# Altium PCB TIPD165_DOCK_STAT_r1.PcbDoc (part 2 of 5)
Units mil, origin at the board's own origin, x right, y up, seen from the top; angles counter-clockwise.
Board outline 6950 x 2800 mil, 2 copper layers (Primary Side, Secondary Side), stack 12.7 mil thick; 32 components, 163 nets, 1211 pads, 80 vias.
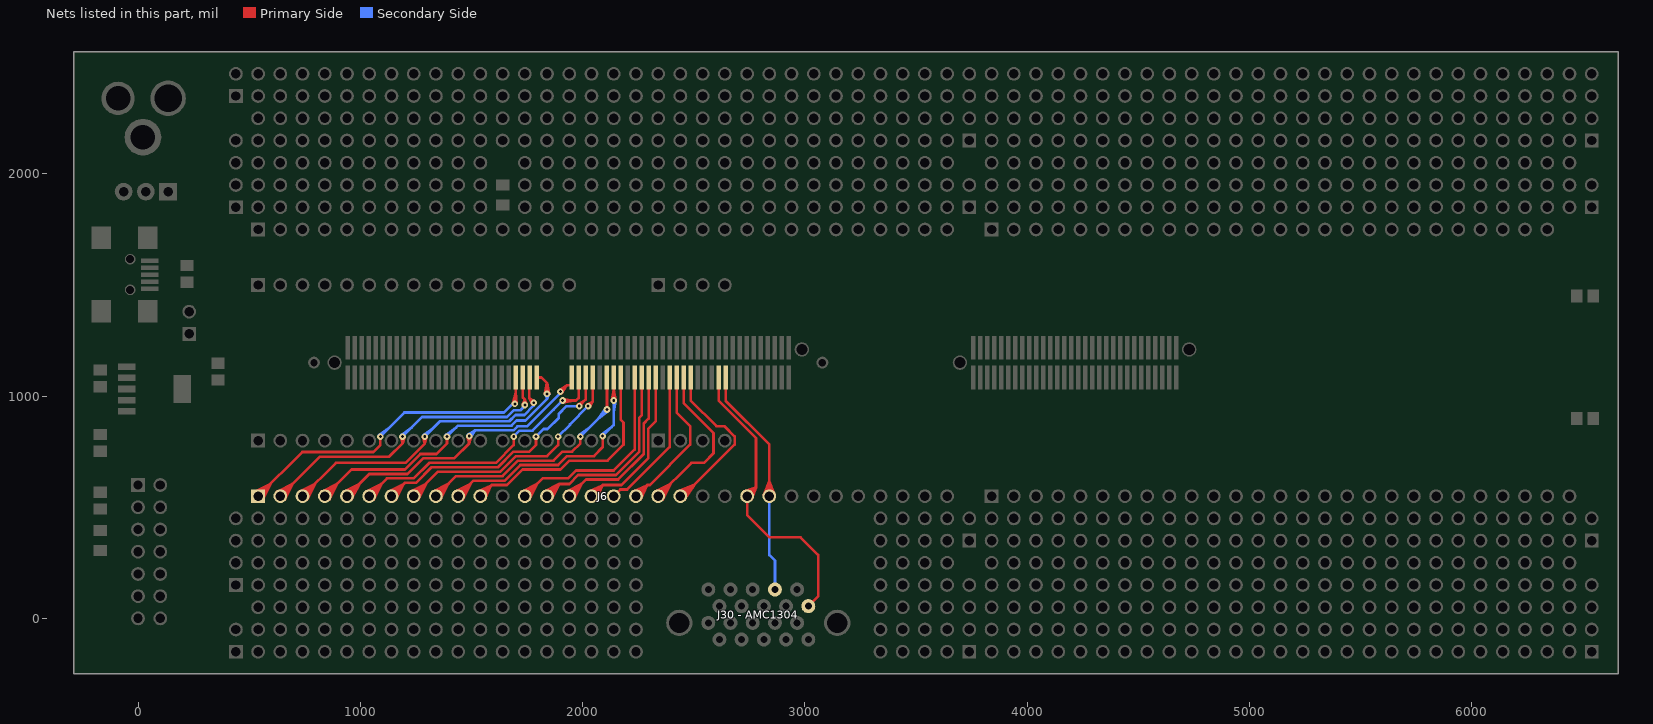
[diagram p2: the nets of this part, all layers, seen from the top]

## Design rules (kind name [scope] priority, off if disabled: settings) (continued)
PolygonConnect "Polygon Connect Style - Primary Side Square SMD from global defaults 1" [IsSMTPin And (PadShape_TopLayer = 'Rectangular') And (PadXSize_TopLayer = PADYSize_TopLayer) vs Layer = 'Primary Side'] p6: connectstyle=Relief reliefconductorwidth=10 reliefentries=4 polygonreliefangle="45 Angle" airgapwidth=10
PolygonConnect "Polygon Connect Style - Primary Side Square SMD from global defaults 2" [IsSMTPin And (PadShape_TopLayer = 'Octagonal') And (PadXSize_TopLayer = PADYSize_TopLayer) vs Layer = 'Primary Side'] p7: connectstyle=Relief reliefconductorwidth=10 reliefentries=4 polygonreliefangle="45 Angle" airgapwidth=10
PolygonConnect "Polygon Connect Style - Primary Side Square SMD from global defaults 3" [IsSMTPin And (PadShape_TopLayer = 'Rounded Rectangle') And (PadXSize_TopLayer = PADYSize_TopLayer) vs Layer = 'Primary Side'] p8: connectstyle=Relief reliefconductorwidth=10 reliefentries=4 polygonreliefangle="45 Angle" airgapwidth=10
PolygonConnect "Polygon Connect Style - Secondary Side Rect SMD from global defaults 1" [IsSMTPin And (PadShape_BottomLayer = 'Rectangular') And (PadXSize_BottomLayer <> PADYSize_BottomLayer) vs Layer = 'Secondary Side'] p9: connectstyle=Direct reliefconductorwidth=10 reliefentries=4 polygonreliefangle="45 Angle" airgapwidth=10
PolygonConnect "Polygon Connect Style - Secondary Side Rect SMD from global defaults 2" [IsSMTPin And (PadShape_BottomLayer = 'Octagonal') And (PadXSize_BottomLayer <> PADYSize_BottomLayer) vs Layer = 'Secondary Side'] p10: connectstyle=Direct reliefconductorwidth=10 reliefentries=4 polygonreliefangle="45 Angle" airgapwidth=10
PolygonConnect "Polygon Connect Style - Secondary Side Rect SMD from global defaults 3" [IsSMTPin And (PadShape_BottomLayer = 'Rounded Rectangle') And (PadXSize_BottomLayer <> PADYSize_BottomLayer) vs Layer = 'Secondary Side'] p11: connectstyle=Direct reliefconductorwidth=10 reliefentries=4 polygonreliefangle="45 Angle" airgapwidth=10
PolygonConnect "Polygon Connect Style - Secondary Side Square-rect SMD pad from global defaults" [IsSMTPin And (PadShape_BottomLayer = 'Rounded Rectangle') And (PadXSize_BottomLayer = PADYSize_BottomLayer) And (Pad_CornerRadius_BottomLayer = '0%') vs Layer = 'Secondary Side'] p12: connectstyle=Direct reliefconductorwidth=10 reliefentries=4 polygonreliefangle="45 Angle" airgapwidth=10
PolygonConnect "Polygon Connect Style - Primary Side Rect SMD from global defaults 1" [IsSMTPin And (PadShape_TopLayer = 'Rectangular') And (PadXSize_TopLayer <> PADYSize_TopLayer) vs Layer = 'Primary Side'] p13: connectstyle=Direct reliefconductorwidth=10 reliefentries=4 polygonreliefangle="45 Angle" airgapwidth=10
PolygonConnect "Polygon Connect Style - Primary Side Rect SMD from global defaults 2" [IsSMTPin And (PadShape_TopLayer = 'Octagonal') And (PadXSize_TopLayer <> PADYSize_TopLayer) vs Layer = 'Primary Side'] p14: connectstyle=Direct reliefconductorwidth=10 reliefentries=4 polygonreliefangle="45 Angle" airgapwidth=10
PolygonConnect "Polygon Connect Style - Primary Side Rect SMD from global defaults 3" [IsSMTPin And (PadShape_TopLayer = 'Rounded Rectangle') And (PadXSize_TopLayer <> PADYSize_TopLayer) vs Layer = 'Primary Side'] p15: connectstyle=Direct reliefconductorwidth=10 reliefentries=4 polygonreliefangle="45 Angle" airgapwidth=10
PolygonConnect "Polygon Connect Style - Primary Side Square-rect SMD pad from global defaults" [IsSMTPin And (PadShape_TopLayer = 'Rounded Rectangle') And (PadXSize_TopLayer = PADYSize_TopLayer) And (Pad_CornerRadius_TopLayer = '0%') vs Layer = 'Primary Side'] p16: connectstyle=Direct reliefconductorwidth=10 reliefentries=4 polygonreliefangle="45 Angle" airgapwidth=10
PolygonConnect "Polygon Connect Style - Secondary Side Oval SMD from global defaults" [IsSMTPin And (PadShape_BottomLayer = 'Round') And (PadXSize_BottomLayer <> PADYSize_BottomLayer) vs Layer = 'Secondary Side'] p17: connectstyle=Relief reliefconductorwidth=10 reliefentries=4 polygonreliefangle="45 Angle" airgapwidth=10
PolygonConnect "Polygon Connect Style - Secondary Side Round-oval SMD pad from global defaults" [IsSMTPin And (PadShape_BottomLayer = 'Rounded Rectangle') And (PadXSize_BottomLayer = PADYSize_BottomLayer) And (Pad_CornerRadius_BottomLayer = '100%') vs Layer = 'Secondary Side'] p18: connectstyle=Relief reliefconductorwidth=10 reliefentries=4 polygonreliefangle="45 Angle" airgapwidth=10
PolygonConnect "Polygon Connect Style - Primary Side Oval SMD from global defaults" [IsSMTPin And (PadShape_TopLayer = 'Round') And (PadXSize_TopLayer <> PADYSize_TopLayer) vs Layer = 'Primary Side'] p19: connectstyle=Relief reliefconductorwidth=10 reliefentries=4 polygonreliefangle="45 Angle" airgapwidth=10
PolygonConnect "Polygon Connect Style - Primary Side Round-oval SMD pad from global defaults" [IsSMTPin And (PadShape_TopLayer = 'Rounded Rectangle') And (PadXSize_TopLayer = PADYSize_TopLayer) And (Pad_CornerRadius_TopLayer = '100%') vs Layer = 'Primary Side'] p20: connectstyle=Relief reliefconductorwidth=10 reliefentries=4 polygonreliefangle="45 Angle" airgapwidth=10
PolygonConnect "Polygon Connect Style - Via from round thru-hole global defaults_19" [IsVia] p21: connectstyle=Relief reliefconductorwidth=25 reliefentries=4 polygonreliefangle="45 Angle" airgapwidth=10
PolygonConnect "Polygon Connect Style - Secondary Side Round thru-hole pad from global defaults" [IsPad And OnMultiLayer And (PadShape_BottomLayer = 'Round') And (PadXSize_BottomLayer = PADYSize_BottomLayer) vs Layer = 'Secondary Side'] p22: connectstyle=Relief reliefconductorwidth=25 reliefentries=4 polygonreliefangle="45 Angle" airgapwidth=10
PolygonConnect "Polygon Connect Style - Via from round thru-hole global defaults" [IsVia] p23: connectstyle=Relief reliefconductorwidth=25 reliefentries=4 polygonreliefangle="45 Angle" airgapwidth=10
PolygonConnect "Polygon Connect Style - Primary Side Round thru-hole pad from global defaults" [IsPad And OnMultiLayer And (PadShape_TopLayer = 'Round') And (PadXSize_TopLayer = PADYSize_TopLayer) vs Layer = 'Primary Side'] p24: connectstyle=Relief reliefconductorwidth=25 reliefentries=4 polygonreliefangle="45 Angle" airgapwidth=10
PolygonConnect "Polygon Connect Style - Secondary Side Square thru-hole pad from global defaults" [IsPad And OnMultiLayer And ((PadShape_BottomLayer = 'Rectangular') Or (PadShape_BottomLayer = 'Octagonal') Or (PadShape_BottomLayer = 'Rounded Rectangle')) And (PadXSize_BottomLayer = PADYSize_BottomLayer) vs Layer = 'Secondary Side'] p25: connectstyle=Relief reliefconductorwidth=25 reliefentries=4 polygonreliefangle="45 Angle" airgapwidth=10
PolygonConnect "Polygon Connect Style - Primary Side Square thru-hole pad from global defaults" [IsPad And OnMultiLayer And ((PadShape_TopLayer = 'Rectangular') Or (PadShape_TopLayer = 'Octagonal') Or (PadShape_TopLayer = 'Rounded Rectangle')) And (PadXSize_TopLayer = PADYSize_TopLayer) vs Layer = 'Primary Side'] p26: connectstyle=Relief reliefconductorwidth=25 reliefentries=4 polygonreliefangle="45 Angle" airgapwidth=10
PolygonConnect "Polygon Connect Style - Secondary Side Rect thru-hole pad from global defaults" [IsPad And OnMultiLayer And ((PadShape_BottomLayer = 'Rectangular') Or (PadShape_BottomLayer = 'Octagonal') Or (PadShape_BottomLayer = 'Rounded Rectangle')) And (PadXSize_BottomLayer <> PADYSize_BottomLayer) vs Layer = 'Secondary Side'] p27: connectstyle=Direct reliefconductorwidth=25 reliefentries=4 polygonreliefangle="45 Angle" airgapwidth=10
PolygonConnect "Polygon Connect Style - Secondary Side Square-rect thru-hole pad from global defaults" [IsPad And OnMultiLayer And (PadShape_BottomLayer = 'Rounded Rectangle') And (PadXSize_BottomLayer = PADYSize_BottomLayer) And (Pad_CornerRadius_BottomLayer = '0%') vs Layer = 'Secondary Side'] p28: connectstyle=Direct reliefconductorwidth=25 reliefentries=4 polygonreliefangle="45 Angle" airgapwidth=10
PolygonConnect "Polygon Connect Style - Primary Side Rect thru-hole pad from global defaults" [IsPad And OnMultiLayer And ((PadShape_TopLayer = 'Rectangular') Or (PadShape_TopLayer = 'Octagonal') Or (PadShape_TopLayer = 'Rounded Rectangle')) And (PadXSize_TopLayer <> PADYSize_TopLayer) vs Layer = 'Primary Side'] p29: connectstyle=Direct reliefconductorwidth=25 reliefentries=4 polygonreliefangle="45 Angle" airgapwidth=10
PolygonConnect "Polygon Connect Style - Primary Side Square-rect thru-hole pad from global defaults" [IsPad And OnMultiLayer And (PadShape_TopLayer = 'Rounded Rectangle') And (PadXSize_TopLayer = PADYSize_TopLayer) And (Pad_CornerRadius_TopLayer = '0%') vs Layer = 'Primary Side'] p30: connectstyle=Direct reliefconductorwidth=25 reliefentries=4 polygonreliefangle="45 Angle" airgapwidth=10
PolygonConnect "Polygon Connect Style - Secondary Side Oval thru-hole pad from global defaults" [IsPad And OnMultiLayer And (PadShape_BottomLayer = 'Round') And (PadXSize_BottomLayer <> PADYSize_BottomLayer) vs Layer = 'Secondary Side'] p31: connectstyle=Relief reliefconductorwidth=25 reliefentries=4 polygonreliefangle="45 Angle" airgapwidth=10
PolygonConnect "Polygon Connect Style - Secondary Side Round-oval thru-hole pad from global defaults" [IsPad And OnMultiLayer And (PadShape_BottomLayer = 'Rounded Rectangle') And (PadXSize_BottomLayer = PADYSize_BottomLayer) And (Pad_CornerRadius_BottomLayer = '100%') vs Layer = 'Secondary Side'] p32: connectstyle=Relief reliefconductorwidth=25 reliefentries=4 polygonreliefangle="45 Angle" airgapwidth=10
PolygonConnect "Polygon Connect Style - Primary Side Oval thru-hole pad from global defaults" [IsPad And OnMultiLayer And (PadShape_TopLayer = 'Round') And (PadXSize_TopLayer <> PADYSize_TopLayer) vs Layer = 'Primary Side'] p33: connectstyle=Relief reliefconductorwidth=25 reliefentries=4 polygonreliefangle="45 Angle" airgapwidth=10
PolygonConnect "Polygon Connect Style - Primary Side Round-oval thru-hole pad from global defaults" [IsPad And OnMultiLayer And (PadShape_TopLayer = 'Rounded Rectangle') And (PadXSize_TopLayer = PADYSize_TopLayer) And (Pad_CornerRadius_TopLayer = '100%') vs Layer = 'Primary Side'] p34: connectstyle=Relief reliefconductorwidth=25 reliefentries=4 polygonreliefangle="45 Angle" airgapwidth=10
PolygonConnect [All] p35: connectstyle=Relief reliefconductorwidth=10 reliefentries=4 polygonreliefangle="90 Angle" airgapwidth=10
RoutingLayers "'Default' PADS rule_3" [All] p1: top layer_v5=TRUE bottom layer_v5=TRUE
RoutingPriority "'Default' PADS rule_2" [All] p1: routingpriority=3
RoutingTopology "'Default' PADS rule" [All] p1: topology=Shortest
RoutingVias "'Default' PADS rule_4" [All] p1: holewidth=13 width=30 viastyle="Through Hole" minholewidth=13 minwidth=30 maxholewidth=13 maxwidth=30
SMDToCorner "'Default' PADS rule_16" [All] p1: distance=60000
SMDToPlane "'Default' PADS rule_17" [All] p1: distance=60000
SilkscreenOverComponentPads [All] p1: minsilkscreentomaskgap=10
SolderMaskExpansion [All] p1: expansion=4
Width "'Default' PADS rule_13" [All] p1: maxlimit=200 minlimit=6 preferedwidth=12
21 further rules are at their usual default settings.

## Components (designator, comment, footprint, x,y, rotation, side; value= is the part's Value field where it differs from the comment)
C1 "C0805" C0805 360,1110 r90 top
C2 "C0805" C0805 -170,790 r90 top
C3 "C0805" C0805 -170,1080 r270 top
C4 "C0805" C0805 220,1550 r90 top
C5 "C0805" C0805 6510,900 r0 top
C6 "C0805" C0805 6510,1450 r0 top
D1 "LED0805" LED0805 -170,530 r270 top
J1 "CONN_PWR_JACK_2.1ID_5.5OD" CONN_PWR_JACK_2.1ID_5.5OD -90,2340 r0 top
J2 "HEADER_7X2_100" HEADER_7X2_100 0,600 r270 top
J6 "HEADER_1X32_100" HEADER_1X32_100 540,550 r0 top
J7 "HEADER_1X32_100" HEADER_1X32_100 540,1750 r0 top
J9 "HEADER_1X26_100" HEADER_1X26_100 3840,1750 r0 top
J10 "HEADER_1X4_100" HEADER_1X4_100 2340,800 r0 top
J11 "HEADER_1X4_100" HEADER_1X4_100 2340,1500 r0 top
J12 "HEADER_1X2_100" HEADER_1X2_100 440,-150 r90 top
J13 "HEADER_1X2_100" HEADER_1X2_100 440,2350 r90 top
J14 "HEADER_1X4_100" HEADER_1X4_100 440,150 r90 top
J15 "HEADER_1X4_100" HEADER_1X4_100 440,1850 r90 top
J16 "HEADER_1X2_100" HEADER_1X2_100 230,1280 r90 top
J17 "CONN_USB_B_MINI_FEMALE" CONN_USB_B_MINI_FEMALE 53,1547 r270 top
J18 "HEADER_1X4_100" HEADER_1X4_100 3740,-150 r90 top
J19 "HEADER_1X2_100" HEADER_1X2_100 3740,350 r90 top
J20 "HEADER_1X4_100" HEADER_1X4_100 3740,2150 r90 top
J22 "HEADER_1X4_100" HEADER_1X4_100 6540,-150 r90 top
J23 "HEADER_1X2_100" HEADER_1X2_100 6540,350 r90 top
J24 "HEADER_1X4_100" HEADER_1X4_100 6540,2150 r90 top
J25 "HEADER_1X2_100" HEADER_1X2_100 6540,1850 r90 top
"J30 - AMC1304" "Comment" FX2_20P_1P27_DS_HEAD_GOOD 3145.63,-20 r180 top
R1 "R0805" R0805 -170,350 r90 top
R2 "R0805" R0805 1640,1905 r90 top
S1 "SWITCH_108-2AS3T1205-EVX" SWITCH_108-2AS3T1205-EVX 135,1920 r270 top
U1 "SOT-223-6" SOT-223-6 74,1032 r270 top

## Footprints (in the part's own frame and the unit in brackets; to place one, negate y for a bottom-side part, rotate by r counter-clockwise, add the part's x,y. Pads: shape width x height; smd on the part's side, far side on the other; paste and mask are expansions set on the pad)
C0805 [mil]
  rect 51x59 smd mask+3: 1(-37.5,0) 2(37.5,0)
  silkscreen extent -78,-45 78,45
CONN_PWR_JACK_2.1ID_5.5OD [mil]
  round 150 hole 110 mask+3: 1(0,0)
  round 160 hole 124 mask+3: 2(225,0)
  round 165 hole 110 mask+3: 3(112,-175)
  silkscreen extent -200,-275 325,150
CONN_USB_B_MINI_FEMALE [mil]
  rect 20x80 smd mask+3: 1(-62.99,0) 2(-31.5,0) 3(0,0) 4(31.5,0) 5(62.99,0)
  rect 100x88 smd mask+3: 6(-165.35,-9.84) 7(165.35,-9.84) 8(-165.35,-218.5) 9(165.35,-218.5)
  round 48 hole 36 unplated mask+10: 10(-68.9,-88.58)
  round 48 hole 36 unplated mask+7: 11(68.9,-88.58)
  silkscreen extent -152,-343 152,50
FX2_20P_1P27_DS_HEAD_GOOD [mm] "Hirose FX2-20P-1.27DS: CONN HEADER Right Angle 20POS 1.27MM."
  round 1.6 hole 0.8: a1(3.31,-1.905) a2(4.58,-3.81) a3(5.85,-1.905) a4(7.12,-3.81) a5(8.39,-1.905) a6(9.66,-3.81) a7(10.93,-1.905) a8(12.2,-3.81) a9(13.47,-1.905) a10(14.74,-3.81) b1(3.31,1.905) b2(4.58,0) b3(5.85,1.905) b4(7.12,0) b5(8.39,1.905) b6(9.66,0) b7(10.93,1.905) b8(12.2,0) b9(13.47,1.905) b10(14.74,0)
  round 3 hole 2.3: m0(0,0) m1(18.05,0)
  silkscreen extent -3,-5 21.05,4.95, body extent -2.35,-4.59 20.4,10.41, height 7.7
HEADER_1X2_100 [mil]
  rect 62x62 / inner round 62 / far side rect 62x62 hole 42 mask+3: 1(0,0)
  round 62 hole 42 mask+3: 2(100,0)
  silkscreen extent -50,-50 150,50
HEADER_1X4_100 [mil]
  rect 62x62 / inner round 62 / far side rect 62x62 hole 42 mask+3: 1(0,0)
  round 62 hole 42 mask+3: 2(100,0) 3(200,0) 4(300,0)
  silkscreen extent -50,-50 350,50
HEADER_1X26_100 [mil]
  rect 62x62 / inner round 62 / far side rect 62x62 hole 42 mask+3: 1(0,0)
  round 62 hole 42 mask+3: 2(100,0) 3(200,0) 4(300,0) 5(400,0) 6(500,0) 7(600,0) 8(700,0) 9(800,0) 10(900,0) 11(1000,0) 12(1100,0) 13(1200,0) 14(1300,0) 15(1400,0) 16(1500,0) 17(1600,0) 18(1700,0) 19(1800,0) 20(1900,0) 21(2000,0) 22(2100,0) 23(2200,0) 24(2300,0) 25(2400,0) 26(2500,0)
  silkscreen extent -50,-50 2550,50
HEADER_1X32_100 [mil]
  rect 62x62 / inner round 62 / far side rect 62x62 hole 42 mask+3: 1(0,0)
  round 62 hole 42 mask+3: 2(100,0) 3(200,0) 4(300,0) 5(400,0) 6(500,0) 7(600,0) 8(700,0) 9(800,0) 10(900,0) 11(1000,0) 12(1100,0) 13(1200,0) 14(1300,0) 15(1400,0) 16(1500,0) 17(1600,0) 18(1700,0) 19(1800,0) 20(1900,0) 21(2000,0) 22(2100,0) 23(2200,0) 24(2300,0) 25(2400,0) 26(2500,0) 27(2600,0) 28(2700,0) 29(2800,0) 30(2900,0) 31(3000,0) 32(3100,0)
  silkscreen extent -50,-50 3150,50
HEADER_7X2_100 [mil]
  rect 62x62 / inner round 62 / far side rect 62x62 hole 42 mask+3: 1(0,0)
  round 62 hole 42 mask+3: 2(0,100) 3(100,0) 4(100,100) 5(200,0) 6(200,100) 7(300,0) 8(300,100) 9(400,0) 10(400,100) 11(500,0) 12(500,100) 13(600,0) 14(600,100)
  silkscreen extent -50,-50 650,150
LED0805 [mil]
  rect 51x59 smd mask+3: 1(-37.5,0) 2(37.5,0)
  silkscreen extent -99,-35 70,35
R0805 [mil]
  rect 50x60 smd mask+3: 1(-45,0) 2(45,0)
  silkscreen extent -80,-40 80,40
SOT-223-6 [mil]
  rect 30x80 smd mask+3: 1(-100,-125) 2(-50,-125) 3(0,-125) 4(50,-125) 5(100,-125)
  rect 126x80 smd mask+3: 6(0,125)
  silkscreen extent -130,-75 130,70
SWITCH_108-2AS3T1205-EVX [mil]
  rect 80x80 / inner round 80 / far side rect 80x80 hole 43 mask+3: 1(0,0)
  round 80 hole 43 mask+3: 2(0,-100) 3(0,-200)
  silkscreen extent -100,-260 100,60

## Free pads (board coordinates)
  round 62 hole 42 mask+3: 1(540,450) 1(540,2450) 1(3840,450) 1(3840,2450) 2(640,450) 2(640,800) 2(640,1500) 2(640,2450) 2(3740,1950) 2(3940,450) 2(3940,550) 2(3940,2450) 3(740,450) 3(740,800) 3(740,1500) 3(740,2450) 3(4040,450) 3(4040,550) 3(4040,2450) 4(840,450) 4(840,800) 4(840,1500) 4(840,2450) 4(4140,450) 4(4140,550) 4(4140,2450) 5(940,450) 5(940,800) 5(940,1500) 5(940,2450) 5(4240,450) 5(4240,550) 5(4240,2450) 6(1040,450) 6(1040,800) 6(1040,1500) 6(1040,2450) 6(4340,450) 6(4340,550) 6(4340,2450) 7(1140,450) 7(1140,800) 7(1140,1500) 7(1140,2450) 7(4440,450) 7(4440,550) 7(4440,2450) 8(1240,450) 8(1240,800) 8(1240,1500) 8(1240,2450) 8(4540,450) 8(4540,550) 8(4540,2450) 9(1340,450) 9(1340,800) 9(1340,1500) 9(1340,2450) 9(4640,450) 9(4640,550) 9(4640,2450) 10(1440,450) 10(1440,800) 10(1440,1500) 10(1440,2450) 10(4740,450) 10(4740,550) 10(4740,2450) 11(1540,450) 11(1540,800) 11(1540,1500) 11(1540,2450) 11(4840,450) 11(4840,550) 11(4840,2450) 12(1640,450) 12(1640,800) 12(1640,1500) 12(1640,2450) 12(4940,450) 12(4940,550) 12(4940,2450) 13(1740,450) 13(1740,800) 13(1740,1500) 13(1740,2450) 13(5040,450) 13(5040,550) 13(5040,2450) 14(1840,450) 14(1840,800) 14(1840,1500) 14(1840,2450) 14(5140,450) 14(5140,550) 14(5140,2450) 15(1940,450) 15(1940,800) 15(1940,1500) 15(1940,2450) 15(5240,450) 15(5240,550) 15(5240,2450) 16(2040,450) 16(2040,800) 16(2040,2450) 16(5340,450) 16(5340,550) 16(5340,2450) 17(2140,450) 17(2140,800) 17(2140,2450) 17(5440,450) 17(5440,550) 17(5440,2450) 18(2240,450) 18(2240,2450) 18(5540,450) 18(5540,550) 18(5540,2450) 19(2340,2450) 19(5640,450) 19(5640,550) 19(5640,2450) 20(2440,2450) 20(5740,450) 20(5740,550) 20(5740,2450) 21(2540,2450) 21(5840,450) 21(5840,550) 21(5840,2450) 22(2640,2450) 22(5940,450) 22(5940,550) 22(5940,2450) 23(2740,2450) 23(6040,450) 23(6040,550) 23(6040,2450) 24(2840,2450) 24(6140,450) 24(6140,550) 24(6140,2450) 25(2940,2450) 25(6240,450) 25(6240,550) 25(6240,2450) 26(3040,2450) 26(6340,450) 26(6340,550) 26(6340,2450) 27(3140,2450) 27(6440,450) 27(6440,550) 27(6440,2450) 28(3240,2450) 28(3840,350) 28(3840,2350) 29(3340,450) 29(3340,2450) 29(3940,350) 29(3940,2350) 30(3440,450) 30(3440,2450) 30(4040,350) 30(4040,2350) 31(3540,450) 31(3540,2450) 31(4140,350) 31(4140,2350) 32(3640,450) 32(3640,2450) 32(4240,350) 32(4240,2350) 33(540,350) 33(540,2350) 33(4340,350) 33(4340,2350) 34(640,350) 34(640,2350) 34(4440,350) 34(4440,2350) 35(740,350) 35(740,2350) 35(4540,350) 35(4540,2350) 36(840,350) 36(840,2350) 36(4640,350) 36(4640,2350) 37(940,350) 37(940,2350) 37(4740,350) 37(4740,2350) 38(1040,350) 38(1040,2350) 38(4840,350) 38(4840,2350) 39(1140,350) 39(1140,2350) 39(4940,350) 39(4940,2350) 40(1240,350) 40(1240,2350) 40(5040,350) 40(5040,2350) 41(1340,350) 41(1340,2350) 41(5140,350) 41(5140,2350) 42(1440,350) 42(1440,2350) 42(5240,350) 42(5240,2350) 43(1540,350) 43(1540,2350) 43(5340,350) 43(5340,2350) 44(1640,350) 44(1640,2350) 44(5440,350) 44(5440,2350) 45(1740,350) 45(1740,2350) 45(5540,350) 45(5540,2350) 46(1840,350) 46(1840,2350) 46(5640,350) 46(5640,2350) 47(1940,350) 47(1940,2350) 47(5740,350) 47(5740,2350) 48(2040,350) 48(2040,2350) 48(5840,350) 48(5840,2350) 49(2140,350) 49(2140,2350) 49(5940,350) 49(5940,2350) 50(2240,350) 50(2240,2350) 50(6040,350) 50(6040,2350) 51(2340,2350) 51(6140,350) 51(6140,2350) 52(2440,2350) 52(6240,350) 52(6240,2350) 53(2540,2350) 53(6340,350) 53(6340,2350) 54(2640,2350) 54(6440,350) 54(6440,2350) 55(2740,2350) 55(3840,250) 55(3840,2250) 56(2840,2350) 56(3940,250) 56(3940,2250) 57(2940,2350) 57(4040,250) 57(4040,2250) 58(3040,2350) 58(4140,250) 58(4140,2250) 59(3140,2350) 59(4240,250) 59(4240,2250) 60(3240,2350) 60(4340,250) 60(4340,2250) 61(3340,350) 61(3340,2350) 61(4440,250) 61(4440,2250) 62(3440,350) 62(3440,2350) 62(4540,250) 62(4540,2250) 63(3540,350) 63(3540,2350) 63(4640,250) 63(4640,2250) 64(3640,350) 64(3640,2350) 64(4740,250) 64(4740,2250) 65(540,250) 65(540,2250) 65(4840,250) 65(4840,2250) 66(640,250) 66(640,2250) 66(4940,250) 66(4940,2250) 67(740,250) 67(740,2250) 67(5040,250) 67(5040,2250) 68(840,250) 68(840,2250) 68(5140,250) 68(5140,2250) 69(940,250) 69(940,2250) 69(5240,250) 69(5240,2250) 70(1040,250) 70(1040,2250) 70(5340,250) 70(5340,2250) 71(1140,250) 71(1140,2250) 71(5440,250) 71(5440,2250) 72(1240,250) 72(1240,2250) 72(5540,250) 72(5540,2250) 73(1340,250) 73(1340,2250) 73(5640,250) 73(5640,2250) 74(1440,250) 74(1440,2250) 74(5740,250) 74(5740,2250) 75(1540,250) 75(1540,2250) 75(5840,250) 75(5840,2250) 76(1640,250) 76(1640,2250) 76(5940,250) 76(5940,2250) 77(1740,250) 77(1740,2250) 77(6040,250) 77(6040,2250) 78(1840,250) 78(1840,2250) 78(6140,250) 78(6140,2250) 79(1940,250) 79(1940,2250) 79(6240,250) 79(6240,2250) 80(2040,250) 80(2040,2250) 80(6340,250) 80(6340,2250) 81(2140,250) 81(2140,2250) 81(6440,250) 81(6440,2250) 82(2240,250) 82(2240,2250) 82(3840,150) 82(3840,2150) 83(2340,2250) 83(3940,150) 83(3940,2150) 84(2440,2250) 84(4040,150) 84(4040,2150) 85(2540,2250) 85(4140,150) 85(4140,2150) 86(2640,2250) 86(4240,150) 86(4240,2150) 87(2740,2250) 87(4340,150) 87(4340,2150) 88(2840,2250) 88(4440,150) 88(4440,2150) 89(2940,2250) 89(4540,150) 89(4540,2150) 90(3040,2250) 90(4640,150) 90(4640,2150) 91(3140,2250) 91(4740,150) 91(4740,2150) 92(3240,2250) 92(4840,150) 92(4840,2150) 93(3340,250) 93(3340,2250) 93(4940,150) 93(4940,2150) 94(3440,250) 94(3440,2250) 94(5040,150) 94(5040,2150) 95(3540,250) 95(3540,2250) 95(5140,150) 95(5140,2150) 96(3640,250) 96(3640,2250) 96(5240,150) 96(5240,2150) 97(540,150) 97(540,2150) 97(5340,150) 97(5340,2150) 98(640,150) 98(640,2150) 98(5440,150) 98(5440,2150) 99(740,150) 99(740,2150) 99(5540,150) 99(5540,2150) 100(840,150) 100(840,2150) 100(5640,150) 100(5640,2150) 101(940,150) 101(940,2150) 101(5740,150) 101(5740,2150) 102(1040,150) 102(1040,2150) 102(5840,150) 102(5840,2150) 103(1140,150) 103(1140,2150) 103(5940,150) 103(5940,2150) 104(1240,150) 104(1240,2150) 104(6040,150) 104(6040,2150) 105(1340,150) 105(1340,2150) 105(6140,150) 105(6140,2150) 106(1440,150) 106(1440,2150) 106(6240,150) 106(6240,2150) 107(1540,150) 107(1540,2150) 107(6340,150) 107(6340,2150) 108(1640,150) 108(1640,2150) 108(6440,150) 108(6440,2150) 109(1740,150) 109(1740,2150) 109(3840,50) 109(3840,2050) 110(1840,150) 110(1840,2150) 110(3940,50) 110(3940,2050) 111(1940,150) 111(1940,2150) 111(4040,50) 111(4040,2050) 112(2040,150) 112(2040,2150) 112(4140,50) 112(4140,2050) 113(2140,150) 113(2140,2150) 113(4240,50) 113(4240,2050) 114(2240,150) 114(2240,2150) 114(4340,50) 114(4340,2050) 115(2340,2150) 115(4440,50) 115(4440,2050) 116(2440,2150) 116(4540,50) 116(4540,2050) 117(2540,2150) 117(4640,50) 117(4640,2050) 118(2640,2150) 118(4740,50) 118(4740,2050) 119(2740,2150) 119(4840,50) 119(4840,2050) 120(2840,2150) 120(4940,50) 120(4940,2050) 121(2940,2150) 121(5040,50) 121(5040,2050) 122(3040,2150) 122(5140,50) 122(5140,2050) 123(3140,2150) 123(5240,50) 123(5240,2050) 124(3240,2150) 124(5340,50) 124(5340,2050) 125(3340,150) 125(3340,2150) 125(5440,50) 125(5440,2050) 126(3440,150) 126(3440,2150) 126(5540,50) 126(5540,2050) 127(3540,150) 127(3540,2150) 127(5640,50) 127(5640,2050) 128(3640,150) 128(3640,2150) 128(5740,50) 128(5740,2050) 129(540,50) 129(540,2050) 129(5840,50) 129(5840,2050) 130(640,50) 130(640,2050) 130(5940,50) 130(5940,2050) 131(740,50) 131(740,2050) 131(6040,50) 131(6040,2050) 132(840,50) 132(840,2050) 132(6140,50) 132(6140,2050) 133(940,50) 133(940,2050) 133(6240,50) 133(6240,2050) 134(1040,50) 134(1040,2050) 134(6340,50) 134(6340,2050) 135(1140,50) 135(1140,2050) 135(6440,50) 135(6440,2050) 136(1240,50) 136(1240,2050) 136(3840,-50) 136(3840,1950) 137(1340,50) 137(1340,2050) 137(3940,-50) 137(3940,1950) 138(1440,50) 138(1440,2050) 138(4040,-50) 138(4040,1950) 139(1540,50) 139(1540,2050) 139(4140,-50) 139(4140,1950) 140(1640,50) 140(4240,-50) 140(4240,1950) 141(1740,50) 141(1740,2050) 141(4340,-50) 141(4340,1950) 142(1840,50) 142(1840,2050) 142(4440,-50) 142(4440,1950) 143(1940,50) 143(1940,2050) 143(4540,-50) 143(4540,1950) 144(2040,50) 144(2040,2050) 144(4640,-50) 144(4640,1950) 145(2140,50) 145(2140,2050) 145(4740,-50) 145(4740,1950) 146(2240,50) 146(2240,2050) 146(4840,-50) 146(4840,1950) 147(2340,2050) 147(4940,-50) 147(4940,1950) 148(2440,2050) 148(5040,-50) 148(5040,1950) 149(2540,2050) 149(5140,-50) 149(5140,1950) 150(2640,2050) 150(5240,-50) 150(5240,1950) 151(2740,2050) 151(5340,-50) 151(5340,1950) 152(2840,2050) 152(5440,-50) 152(5440,1950) 153(2940,2050) 153(5540,-50) 153(5540,1950) 154(3040,2050) 154(5640,-50) 154(5640,1950) 155(3140,2050) 155(5740,-50) 155(5740,1950) 156(3240,2050) 156(5840,-50) 156(5840,1950) 157(3340,50) 157(3340,2050) 157(5940,-50) 157(5940,1950) 158(3440,50) 158(3440,2050) 158(6040,-50) 158(6040,1950) 159(3540,50) 159(3540,2050) 159(6140,-50) 159(6140,1950) 160(3640,50) 160(3640,2050) 160(6240,-50) 160(6240,1950) 161(540,-50) 161(540,1950) 161(6340,-50) 161(6340,1950) 162(640,-50) 162(640,1950) 162(6440,-50) 162(6440,1950) 163(740,-50) 163(740,1950) 163(3840,-150) 163(3840,1850) 164(840,-50) 164(840,1950) 164(3940,-150) 164(3940,1850) 165(940,-50) 165(940,1950) 165(4040,-150) 165(4040,1850) 166(1040,-50) 166(1040,1950) 166(4140,-150) 166(4140,1850) 167(1140,-50) 167(1140,1950) 167(4240,-150) 167(4240,1850) 168(1240,-50) 168(1240,1950) 168(4340,-150) 168(4340,1850) 169(1340,-50) 169(1340,1950) 169(4440,-150) 169(4440,1850) 170(1440,-50) 170(1440,1950) 170(4540,-150) 170(4540,1850) 171(1540,-50) 171(1540,1950) 171(4640,-150) 171(4640,1850) 172(1640,-50) 172(4740,-150) 172(4740,1850) 173(1740,-50) 173(1740,1950) 173(4840,-150) 173(4840,1850) 174(1840,-50) 174(1840,1950) 174(4940,-150) 174(4940,1850) 175(1940,-50) 175(1940,1950) 175(5040,-150) 175(5040,1850) 176(2040,-50) 176(2040,1950) 176(5140,-150) 176(5140,1850) 177(2140,-50) 177(2140,1950) 177(5240,-150) 177(5240,1850) 178(2240,-50) 178(2240,1950) 178(5340,-150) 178(5340,1850) 179(2340,1950) 179(5440,-150) 179(5440,1850) 180(2440,1950) 180(5540,-150) 180(5540,1850) 181(2540,1950) 181(5640,-150) 181(5640,1850) 182(2640,1950) 182(5740,-150) 182(5740,1850) 183(2740,1950) 183(5840,-150) 183(5840,1850) 184(2840,1950) 184(5940,-150) 184(5940,1850) 185(2940,1950) 185(6040,-150) 185(6040,1850) 186(3040,1950) 186(6140,-150) 186(6140,1850) 187(3140,1950) 187(6240,-150) 187(6240,1850) 188(3240,1950) 188(6340,-150) 188(6340,1850) 189(3340,-50) 189(3340,1950) 189(6440,-150) 189(6440,1850) 190(3440,-50) 190(3440,1950) 191(3540,-50) 191(3540,1950) 192(3640,-50) 192(3640,1950) 193(540,-150) 193(540,1850) 194(640,-150) 194(640,1850) 195(740,-150) 195(740,1850) 196(840,-150) 196(840,1850) 197(940,-150) 197(940,1850) 198(1040,-150) 198(1040,1850) 199(1140,-150) 199(1140,1850) 200(1240,-150) 200(1240,1850) 201(1340,-150) 201(1340,1850) 202(1440,-150) 202(1440,1850) 203(1540,-150) 203(1540,1850) 204(1640,-150) 205(1740,-150) 205(1740,1850) 206(1840,-150) 206(1840,1850) 207(1940,-150) 207(1940,1850) 208(2040,-150) 208(2040,1850) 209(2140,-150) 209(2140,1850) 210(2240,-150) 210(2240,1850) 211(2340,1850) 212(2440,1850) 213(2540,1850) 214(2640,1850) 215(2740,1850) 216(2840,1850) 217(2940,1850) 218(3040,1850) 219(3140,1850) 220(3240,1850) 221(3340,-150) 221(3340,1850) 222(3440,-150) 222(3440,1850) 223(3540,-150) 223(3540,1850) 224(3640,-150) 224(3640,1850)
  rect 62x62 / inner round 62 / far side rect 62x62 hole 42 mask+3: 1(540,800) 1(540,1500) 1(3740,1850) 1(3840,550)
  rect 19.68x107.24 smd mask+3: 1(943,1084) 2(943,1217.86) 3(974.5,1084) 4(974.5,1217.86) 5(1005.99,1084) 6(1005.99,1217.86) 7(1037.49,1084) 8(1037.49,1217.86) 9(1068.98,1084) 10(1068.98,1217.86) 11(1100.48,1084) 12(1100.48,1217.86) 13(1131.98,1084) 14(1131.98,1217.86) 15(1163.47,1084) 16(1163.47,1217.86) 17(1194.97,1084) 18(1194.97,1217.86) 19(1226.46,1084) 20(1226.46,1217.86) 21(1257.96,1084) 22(1257.96,1217.86) 23(1289.46,1084) 24(1289.46,1217.86) 25(1320.95,1084) 26(1320.95,1217.86) 27(1352.45,1084) 28(1352.45,1217.86) 29(1383.94,1084) 30(1383.94,1217.86) 31(1415.44,1084) 32(1415.44,1217.86) 33(1446.94,1084) 34(1446.94,1217.86) 35(1478.43,1084) 36(1478.43,1217.86) 37(1509.93,1084) 38(1509.93,1217.86) 39(1541.43,1084) 40(1541.43,1217.86) 41(1572.92,1084) 42(1572.92,1217.86) 43(1604.42,1084) 44(1604.42,1217.86) 45(1635.91,1084) 46(1635.91,1217.86) 47(1667.41,1084) 48(1667.41,1217.86) 49(1698.91,1084) 50(1698.91,1217.86) 51(1730.4,1084) 52(1730.4,1217.86) 53(1761.9,1084) 54(1761.9,1217.86) 55(1793.39,1084) 56(1793.39,1217.86) 57(1950.87,1084) 58(1950.87,1217.86) 59(1982.37,1084) 60(1982.37,1217.86) 61(2013.87,1084) 62(2013.87,1217.86) 63(2045.36,1084) 64(2045.36,1217.86) 65(2076.86,1084) 66(2076.86,1217.86) 67(2108.35,1084) 68(2108.35,1217.86) 69(2139.85,1084) 70(2139.85,1217.86) 71(2171.35,1084) 72(2171.35,1217.86) 74(2202.84,1217.86) 75(2234.34,1084) 76(2234.34,1217.86) 77(2265.83,1084) 78(2265.83,1217.86) 79(2297.33,1084) 80(2297.33,1217.86) 81(2328.83,1084) 82(2328.83,1217.86) 84(2360.32,1217.86) 85(2391.82,1084) 86(2391.82,1217.86) 87(2423.31,1084) 88(2423.31,1217.86) 89(2454.81,1084) 90(2454.81,1217.86) 91(2486.31,1084) 92(2486.31,1217.86) 93(2517.8,1084) 94(2517.8,1217.86) 95(2549.3,1084) 96(2549.3,1217.86) 97(2580.8,1084) 98(2580.8,1217.86) 99(2612.29,1084) 100(2612.29,1217.86) 101(2643.79,1084) 102(2643.79,1217.86) 103(2675.28,1084) 104(2675.28,1217.86) 105(2706.78,1084) 106(2706.78,1217.86) 107(2738.28,1084) 108(2738.28,1217.86) 109(2769.77,1084) 110(2769.77,1217.86) 111(2801.27,1084) 112(2801.27,1217.86) 113(2832.76,1084) 114(2832.76,1217.86) 115(2864.26,1084) 116(2864.26,1217.86) 117(2895.76,1084) 118(2895.76,1217.86) 119(2927.25,1084) 120(2927.25,1217.86) 121(3756.7,1084) 122(3756.7,1217.86) 123(3788.2,1084) 124(3788.2,1217.86) 125(3819.69,1084) 126(3819.69,1217.86) 127(3851.19,1084) 128(3851.19,1217.86) 129(3882.69,1084) 130(3882.69,1217.86) 131(3914.18,1084) 132(3914.18,1217.86) 133(3945.68,1084) 134(3945.68,1217.86) 135(3977.17,1084) 136(3977.17,1217.86) 137(4008.67,1084) 138(4008.67,1217.86) 139(4040.17,1084) 140(4040.17,1217.86) 141(4071.66,1084) 142(4071.66,1217.86) 143(4103.16,1084) 144(4103.16,1217.86) 145(4134.65,1084) 146(4134.65,1217.86) 147(4166.15,1084) 148(4166.15,1217.86) 149(4197.65,1084) 150(4197.65,1217.86) 151(4229.14,1084) 152(4229.14,1217.86) 153(4260.64,1084) 154(4260.64,1217.86) 155(4292.13,1084) 156(4292.13,1217.86) 157(4323.63,1084) 158(4323.63,1217.86) 159(4355.13,1084) 161(4386.62,1084) 162(4386.62,1217.86) 163(4418.12,1084) 164(4418.12,1217.86) 165(4449.61,1084) 166(4449.61,1217.86) 167(4481.11,1084) 168(4481.11,1217.86) 169(4512.61,1084) 170(4512.61,1217.86) 171(4544.1,1084) 172(4544.1,1217.86) 173(4575.6,1084) 174(4575.6,1217.86) 175(4607.09,1084) 176(4607.09,1217.86) 177(4638.59,1084) 178(4638.59,1217.86) 179(4670.09,1084) 180(4670.09,1217.86)
  rect 19.69x107.24 smd mask+3: 73(2202.84,1084) 83(2360.32,1084) 160(4355.13,1217.86)
  round 65 hole 50 unplated mask+5: 181(883.94,1150.93) 183(3697.65,1150.93)
  round 65 hole 50 unplated mask+6: 182(2986.31,1209.98) 184(4729.14,1209.98)
  round 53.07 hole 33.07: 185(791.43,1150.93) 186(3078.83,1150.93)

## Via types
v1: diameter 30/30 (per signal layer), hole 13, Primary Side to Secondary Side, 70 vias
v2: diameter 62/62 (per signal layer), hole 28, Primary Side to Secondary Side, 9 vias
v3: diameter 30, hole 13, Primary Side to Secondary Side, 1 vias

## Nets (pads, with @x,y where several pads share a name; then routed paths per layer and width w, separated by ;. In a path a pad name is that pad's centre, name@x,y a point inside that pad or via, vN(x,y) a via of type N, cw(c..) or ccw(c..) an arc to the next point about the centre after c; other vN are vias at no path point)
$$$379: J6.1 pad.49@1698.91,1084 | length 2007.3
  Primary Side w12: J6.1@525.31,570.23 596.46,606.46 ; J6.1@531.59,559.91 596.46,606.46 ; J6.1@540,550 739,749 1059,749 1090,780 v1(1090,818) ; J6.1@549.91,541.59 596.46,606.46 ; J6.1@560.23,535.31 596.46,606.46 ; v1@1686.12,966.46 1698.91,1016.51 ; pad.49@1698.91,1084 1698.91,968.91 v1(1695,965) 1698.91,1016.51 ; v1@1704,965.1 1698.91,1016.51
  Secondary Side w12: v1@1084.16,824.84 1130.46,858.46 ; v1(1090,818) 1198,926 1646,926 1685,965 v1(1695,965) v1@1689,965
$$$403: J6.2 pad.51@1730.4,1084 | length 1936.9
  Primary Side w12: J6.2@625.31,570.23 696.46,606.46 ; J6.2@631.59,559.91 696.46,606.46 ; J6.2@640,550 817.77,727.77 1130,727.77 1190,787.77 ; J6.2@649.91,541.59 696.46,606.46 ; J6.2@660.23,535.31 696.46,606.46 ; v1@1181.1,816.66 1190,787.77 ; v1(1190,818) 1190,787.77 ; v1@1198.9,816.66 1190,787.77 ; pad.51@1730.4,1084 1730.4,995 1740,985.4 ; v1@1731.14,961.59 1740,985.4 ; v1(1740,960) 1740,985.4 ; v1@1748.86,961.59 1740,985.4
  Secondary Side w12: v1@1184.16,824.84 1230.46,858.46 ; v1(1190,818) 1278,906 1660,906 1690,936 1720,936 ; 1720,936 1740,956 v1(1740,960) 1720,936
$$$408: J6.3 pad.53@1761.9,1084 | length 1913.2
  Primary Side w12: J6.3@725.31,570.23 796.46,606.46 ; J6.3@731.59,559.91 796.46,606.46 ; J6.3@740,550 890,700 1202.23,700 1290,787.77 ; J6.3@749.91,541.59 796.46,606.46 ; J6.3@760.23,535.31 796.46,606.46 ; v1@1281.1,816.66 1290,787.77 ; v1@1298.9,816.66 1290,787.77 ; pad.53@1761.9,1084 1760,1082.1 1760,990 ; v1@1772.7,964.73 1760,990 ; v1@1785.27,977.3 1760,990 ; 1290,787.77 v1(1290,818) 1290,787.77 ; 1760,990 v1(1780,970) 1760,990
  Secondary Side w12: v1@1284.16,824.84 1330.46,858.46 ; v1(1290,818) 1359,887 1670,887 1698,915 1735,915 ; 1736.42,913.9 1780,957.49 v1(1780,970)
$$$412: J6.4 pad.55@1793.39,1084 | length 1867.7
  Primary Side w12: J6.4@825.31,570.23 896.46,606.46 ; J6.4@831.59,559.91 896.46,606.46 ; J6.4@840,550 960,670 1200,670 1270,740 1342.23,740 1390,787.77 v1(1390,818) ; J6.4@849.91,541.59 896.46,606.46 ; J6.4@860.23,535.31 896.46,606.46 ; pad.55@1793.39,1084 1815,1084 1840,1059 ; v1@1831.04,1010.83 1840,1059 ; v1(1840,1010) 1840,1059 ; v1@1848.96,1010.83 1840,1059
  Secondary Side w12: v1@1384.16,824.84 1430.46,858.46 ; v1(1390,818) 1439,867 1680,867 1703,890 1742,890 1840,988 ; v1@1831.19,1008.16 1840,988 ; v1@1848.81,1008.16 1840,988 ; 1840,988 v1(1840,1010) 1840,988
$$$418: J6.5 pad.57@1950.87,1084 | length 1817.4
  Primary Side w12: J6.5@925.31,570.23 996.46,606.46 ; J6.5@931.59,559.91 996.46,606.46 ; J6.5@940,550 1040,650 1212.52,650 1282.52,720 1422.23,720 1490,787.77 ; J6.5@949.91,541.59 996.46,606.46 ; J6.5@960.23,535.31 996.46,606.46 ; v1@1481.09,818.74 1490,787.77 ; v1(1490,820) 1490,787.77 ; v1@1498.91,818.74 1490,787.77 ; v1@1894.48,1027.11 1930,1049 ; v1(1900,1020) 1930,1049 ; v1@1906.92,1014.24 1930,1049 ; pad.57@1950.87,1084 1950.87,1049 1930,1049
  Secondary Side w12: v1@1484.43,827.07 1517,847 ; v1(1490,820) 1517,847 ; v1@1497.07,814.43 1517,847 ; v1(1900,1020) 1896,1010 1750,864 1707.35,864 1690.35,847 1517,847
$$$422: J6.6 pad.59@1982.37,1084 | length 1718.1
  Primary Side w12: J6.6@1025.31,570.23 1096.46,606.46 ; J6.6@1031.59,559.91 1096.46,606.46 ; J6.6@1040,550 1120,630 1240,630 1310,700 1610,700 1690,780 v1(1690,818) ; J6.6@1049.91,541.59 1096.46,606.46 ; J6.6@1060.23,535.31 1096.46,606.46 ; v1(1910,980) 1970,980 1981.91,991.91 1981.91,1083.54 pad.59@1982.37,1084 ; v1@1910.79,971.04 1961,980 v1@1910.79,988.96
  Secondary Side w12: v1(1690,818) 1716.34,844.34 1774.34,844.34 v1(1910,980) 1869.54,939.54
$$$428: J6.7 pad.61@2013.87,1084 | length 1547
  Primary Side w12: J6.7@1125.31,570.23 1196.46,606.46 ; J6.7@1131.59,559.91 1196.46,606.46 ; J6.7@1140,550 1200,610 1250,610 1320,680 1620,680 1690,750 1760,750 1790,780 v1(1790,818) ; J6.7@1149.91,541.59 1196.46,606.46 ; J6.7@1160.23,535.31 1196.46,606.46 ; v1@1979.37,962.02 2014,984 ; v1(1985,955) 2014,984 ; pad.61@2013.87,1084 2014,1083.87 2014,984
  Secondary Side w12: v1(1790,818) 1824.25,852.25 1842.25,852.25 1892.75,902.75 1892.75,920.75 1927,955 v1(1985,955)
$$$437: J6.8 pad.63@2045.36,1084 | length 1492.9
  Primary Side w12: J6.8@1225.31,570.23 1296.46,606.46 ; J6.8@1231.59,559.91 1296.46,606.46 ; J6.8@1240,550 1350,660 1630,660 1700,730 1840,730 1890,780 v1(1890,818) ; J6.8@1249.91,541.59 1296.46,606.46 ; J6.8@1260.23,535.31 1296.46,606.46 ; v1@2019.67,962.25 2046,976 ; v1(2025,955) 2046,976 ; v1@2032.25,949.67 2046,976 ; pad.63@2045.36,1084 2046,1083.36 2046,976
  Secondary Side w12: v1(1890,818) 1943,871 1943,873 v1(2025,955)
$$$444: J6.9 pad.67@2108.35,1084 | length 1643.4
  Primary Side w12: J6.9@1325.31,570.23 1396.46,606.46 ; J6.9@1331.59,559.91 1396.46,606.46 ; J6.9@1340,550 1430,640 1640,640 1710,710 1870,710 1910,750 1952.23,750 1990,787.77 v1(1990,818) ; J6.9@1349.91,541.59 1396.46,606.46 ; J6.9@1360.23,535.31 1396.46,606.46 ; pad.67@2108.35,1084 2110,1083.35 v1(2110,940)
  Secondary Side w12: v1@1984.16,824.84 2030.46,858.46 ; v1(1990,818) 2110,938 v1(2110,940) 2070.64,898.64 ; v1@2103.01,945.67 2070.64,898.64 ; v1@2116.01,933.3 2070.64,898.64
$$$452: J6.10 pad.69@2139.85,1084 | length 1603.7
  Primary Side w12: J6.10@1425.31,570.23 1496.46,606.46 ; J6.10@1431.59,559.91 1496.46,606.46 ; J6.10@1440,550 1510,620 1650,620 1720,690 1890,690 1930,730 2051,730 2090,770 v1(2090,820) ; J6.10@1449.91,541.59 1496.46,606.46 ; J6.10@1460.23,535.31 1496.46,606.46 ; v1@2131.03,980.78 2139.85,1030 ; pad.69@2139.85,1084 2139.85,1030 ; v1(2140,980) 2139.85,1030 ; v1@2148.96,980.84 2139.85,1030
  Secondary Side w12: v1@2084.16,826.84 2130.46,860.46 ; v1(2090,820) 2140,870 v1(2140,980) ; 2140,929 v1@2148.96,979.21
$$$458: J6.11 pad.71@2171.35,1084 | length 1330.5
  Primary Side w12: J6.11@1525.73,570.52 1590,600 ; J6.11@1531.69,560 1590,600 ; J6.11@1540,550 1590,600 ; J6.11@1550,541.69 1590,600 ; J6.11@1560.52,535.73 1590,600 ; pad.71@2171.35,1084 2171,1077.35 2171,894 2184,881 2184,781.77 2112.23,710 1940,710 1900,670 1730,670 1660,600 1590,600
$$$469: J6.13 pad.75@2234.34,1084 | length 1224.7
  Primary Side w12: J6.13@1725.31,570.23 1796.46,606.46 ; J6.13@1731.59,559.91 1796.46,606.46 ; J6.13@1740,550 1820,630 1934.34,630 1970,665.66 2140,665.66 2234.34,760 pad.75@2234.34,1084 ; J6.13@1749.91,541.59 1796.46,606.46 ; J6.13@1760.23,535.31 1796.46,606.46
$$$5690: J6.14 pad.77@2265.83,1084 | length 1147.5
  Primary Side w12: J6.14@1825.39,570.29 1895,605 ; J6.14@1831.61,559.93 1895,605 ; J6.14@1840,550 1895,605 ; J6.14@1849.93,541.61 1895,605 ; J6.14@1860.29,535.39 1895,605 ; pad.77@2265.83,1084 2265.83,913.83 2255,903 2255,750 2150,645 1980,645 1940,605 1895,605
$$$5696: J6.15 pad.79@2297.33,1084 | length 1086.3
  Primary Side w12: J6.15@1925.31,570.23 1996.46,606.46 ; J6.15@1931.59,559.91 1996.46,606.46 ; J6.15@1940,550 2015,625 2160,625 2275,740 2275,877.18 2297.33,899.51 pad.79@2297.33,1084 ; J6.15@1949.91,541.59 1996.46,606.46 ; J6.15@1960.23,535.31 1996.46,606.46
$$$5701: J6.16 pad.81@2328.83,1084 | length 986.3
  Primary Side w12: J6.16@2025.73,570.52 2090,600 ; J6.16@2031.69,560 2090,600 ; J6.16@2040,550 2090,600 ; J6.16@2050,541.69 2090,600 ; J6.16@2060.52,535.73 2090,600 ; pad.81@2328.83,1084 2328.83,886.67 2295,852.85 2295,720 2175,600 2090,600
$$$5707: J6.17 pad.85@2391.82,1084 | length 656.1
  Primary Side w12: J6.17@2140,550 2170,580 2200.38,580 2391.82,771.43 pad.85@2391.82,1084
$$$5711: J6.18 pad.87@2423.31,1084 | length 950.2
  Primary Side w12: J6.18@2225.73,570.52 2290,600 ; J6.18@2231.69,560 2290,600 ; J6.18@2240,550 2290,600 ; J6.18@2250,541.69 2290,600 ; J6.18@2260.52,535.73 2290,600 ; pad.87@2423.31,1084 2423.31,925.86 2484,865.18 2484,781.77 2302.23,600 2290,600
$$$5881: J6.19 pad.89@2454.81,1084 | length 1044.9
  Primary Side w12: J6.19@2325.31,570.23 2396.46,606.46 ; J6.19@2331.59,559.91 2396.46,606.46 ; J6.19@2340,550 2490,700 2546,700 2589,743 2589,834 2454.81,968.19 pad.89@2454.81,1084 ; J6.19@2349.91,541.59 2396.46,606.46 ; J6.19@2360.23,535.31 2396.46,606.46
$$$5885: J6.20 pad.91@2486.31,1084 | length 1145.1
  Primary Side w12: J6.20@2427.57,571.69 2502.38,600.15 ; J6.20@2432.7,560.76 2502.38,600.15 ; J6.20@2448.94,540.56 2502.38,600.15 ; J6.20@2458.52,533.2 2502.38,600.15 ; pad.91@2486.31,1084 2486.31,980.35 2601.66,865 2637.23,865 2684,818.23 2684,781.77 2452.23,550 J6.20@2440,550 2502.38,600.15
$$$5899: "J30 - AMC1304.a1" J6.23 pad.99@2612.29,1084 | length 1574.2
  Primary Side w12: pad.99@2612.29,1084 2612.29,979.71 2780,812 2780,590 ; J6.23@2726.67,571.15 2780,590 ; J6.23@2731.92,560.19 2780,590 ; J6.23@2750.19,541.92 2780,590 ; J6.23@2761.15,536.67 2780,590 ; 3015.31,55 3059.81,99.5 3059.81,285.19 2980,365 2840,365 2740,465 J6.23@2740,550 2780,590
$$$5910: "J30 - AMC1304.a4" J6.24 pad.101@2643.79,1084 | length 1313.8
  Primary Side w12: pad.101@2643.79,1084 2643.79,979.21 2840,783 J6.24@2840,550 ; J6.24@2815.44,554.66 2840,617 ; J6.24@2827.06,551.26 2840,617 ; J6.24@2852.94,551.26 2840,617 ; J6.24@2864.56,554.66 2840,617
  Secondary Side w12: J6.24@2840,550 2840,285 2865.31,259.69 2865.31,130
